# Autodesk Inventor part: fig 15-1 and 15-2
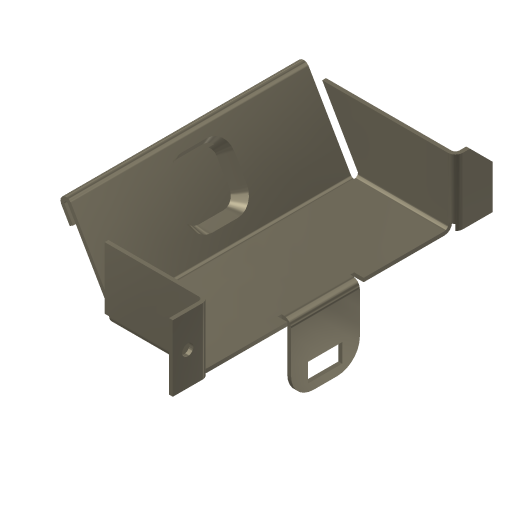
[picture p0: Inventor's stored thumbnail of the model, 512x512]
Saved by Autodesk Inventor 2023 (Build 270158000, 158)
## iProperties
Created: 2002-04
Part Number: fig 15-1 and 15-2
Material: Stainless Steel, 440C
Document SubType Name: Sheet Metal
Density: 1 g/cm^3
Sheet Metal Rule: Default
Appearance: Metal-Titanium (Polished)
Control State: 0
Master: False
Checked Out: False
Shininess: 65.0
Angle Display Precision: 2
Document Length Units: 11269
Document Angle Units: 11279
Document Time Units: 11290
Document Mass Units: 11283
Document Length Units Precision: 3
Document Angle Units Precision: 2
Compacted: False
Density: 0.0
Volumn: 0.0
Area: 0.0
PropertySet Name: Model Information
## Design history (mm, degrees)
node "Face1"
  sketch "Sketch1"
    geometry: L1 (-46.618, 22.343)-(-46.618, -12.657); L2 (-46.618, -12.657)-(53.382, -12.657); L3 (53.382, -12.657)-(53.382, 22.343); L4 (53.382, 22.343)-(35.882, 22.343); L5 (35.882, 22.343)-(35.882, 12.343); L6 (35.882, 12.343)-(-29.118, 12.343); L7 (-29.118, 12.343)-(-29.118, 22.343); L8 (-29.118, 22.343)-(-46.618, 22.343)
    constraints: 16 end point, 6 parallel, 2 equal length, 1 perpendicular, 1 vertical
    dimensions: "d0" = 100 distance of L1.end L2.end; "d1" = 35 distance of L1.start L1.end; "d2" = 65 distance of L5.end L6.end; "d3" = 10 distance of L6.end L7.end
sketch "Sketch2"
  geometry: L1 (100, 0)-(0, 0) reference; L2 (17.5, 35)-(17.5, 25) reference; L3 (17.5, 25)-(17.5, 0); L4 (82.5, 25)-(82.5, 0)
  constraints: 4 end point, 2 point on line, 1 collinear, 1 perpendicular
feature "Fold1" dims "d5" = 1 (= BendRadius), "d6" = 90 deg, "d7" = 1 (= BendRadius), "d52" = 1 (= BendReliefWidth), "d53" = 0.5 (= BendReliefDepth), "d54" = 2 (= MinimumRemnant), "d75" = 1 (= Thickness), "SeamGap" = 0.01
feature "Fold2" dims "d8" = 1 (= BendRadius), "d9" = 90 deg, "d10" = 1 (= BendRadius), "d55" = 1 (= BendReliefWidth), "d56" = 0.5 (= BendReliefDepth), "d57" = 2 (= MinimumRemnant), "d75" = 1 (= Thickness), "SeamGap" = 0.01
node "Flange1"
feature "Corner1" dims "d15" = 1 (= Thickness), "d16" = 0, "d73" = 4 (= CornerReliefSize), "d75" = 1 (= Thickness), "TransitionRadius" = 1 (= BendRadius)
sketch "Sketch4"
  geometry: L1 (0, 0)-(0, 35) reference; L2 (15.869, 25)-(15.869, 26) reference; L3 (17.5, 26)-(0, 26)
  constraints: 2 end point, 1 perpendicular, 1 point on line
feature "Fold3" sketch "Sketch4" dims "d17" = 1 (= BendRadius), "d18" = 90 deg, "d19" = 1 (= BendRadius), "d61" = 1 (= BendReliefWidth), "d62" = 0.5 (= BendReliefDepth), "d63" = 2 (= MinimumRemnant), "d75" = 1 (= Thickness), "SeamGap" = 0.01
sketch "Sketch5"
  geometry: L1 (-17.5, -34.296)-(-17.5, 9) reference; L2 (0, 0)-(-17.5, 0)
  constraints: 2 end point, 1 perpendicular, 1 point on line
feature "Fold4" sketch "Sketch5" dims "d20" = 1 (= BendRadius), "d21" = 90 deg, "d22" = 1 (= BendRadius), "d64" = 1 (= BendReliefWidth), "d65" = 0.5 (= BendReliefDepth), "d66" = 2 (= MinimumRemnant), "d75" = 1 (= Thickness), "SeamGap" = 0.01
sketch "Sketch6"
  geometry: 1 further point
feature "iFeature4:1" sketch "Sketch6"
feature "Hem2" dims "d32" = 1 (= BendRadius), "d33" = 6 (= 6 x Thickness), "d34" = 1 (= Thickness), "d35" = 0.5 (= 0.5 x d34), "d67" = 1 (= BendReliefWidth), "d68" = 0.5 (= BendReliefDepth), "d69" = 2 (= MinimumRemnant), "d75" = 1 (= Thickness), "SeamGap" = 0.01, "MinimumRemnant" = 2 (= 2 x Thickness), "BendReliefWidth" = 1 (= Thickness)
node "Face2"
  sketch "Sketch9"
    geometry: L1 (0, 0)-(62.738, 0) reference; L2 (40.511, 0)-(22.35, 0); L3 (22.35, 0)-(22.35, 18.987); L4 (22.35, 18.987)-(40.511, 18.987); L5 (40.511, 18.987)-(40.511, 0)
    constraints: 8 end point, 2 parallel, 1 horizontal, 1 perpendicular, 1 point on line
sketch "Sketch10"
  geometry: L1 (13.661, -2.202)-(4.661, -2.202); L2 (4.661, -2.202)-(4.661, -7.127); L3 (4.661, -7.127)-(13.661, -7.127); L4 (13.661, -7.127)-(13.661, -2.202); L5 (18.161, -16.987)-(18.161, 0) reference
  constraints: 8 end point, 2 parallel, 1 horizontal, 1 perpendicular
  dimensions: "d50" = 4.5 distance between parallel lines of L5 L4; "d51" = 9 distance of L1.start L1.end
cut "Cut1" sketch "Sketch10" dims "d38" = 1 (= Thickness), "d39" = 0
sketch "Sketch11"
  geometry: 1 further point
hole "Hole1" sketch "Sketch11" at (3.935, 8.75) diameter "d40" = 3; stored, may be unused: countersink angle "d44" = 82 deg, drill point angle "d46" = 118 deg; dims "d41" = 6, "d42" = 4, "d43" = 2, "d45" = 8
feature "Corner Chamfer1" dims "d47" = 6, "d48" = 6, angle "d74" = 45 deg
feature "Corner Round1" dims "d49" = 6
body "Solid1"
face "Plate1" dims "d75" = 1 (= Thickness)
sketch "Sketch3"
  geometry: L1 (-62.738, 0)-(-62.738, 25); L2 (-62.738, 25)-(0, 25); 1 other entity
  constraints: 4 end point, 4 other
face "Plate2" dims "d12" = 25, "d13" = 120 deg, "d14" = 1 (= BendRadius), "d75" = 1 (= Thickness), "MinimumRemnant" = 2 (= 2 x Thickness), "BendReliefWidth" = 1 (= Thickness)
bend "Bend1" dims "d11" = 1 (= BendRadius), "d12" = 25, "d13" = 120 deg, "d14" = 1 (= BendRadius), "d58" = 1 (= BendReliefWidth), "d59" = 0.5 (= BendReliefDepth), "d60" = 2 (= MinimumRemnant), "d75" = 1 (= Thickness), "SeamGap" = 0.01, "MinimumRemnant" = 2 (= 2 x Thickness), "BendReliefWidth" = 1 (= Thickness)
sketch "Sketch8"
  geometry: L1 (0.866, 0.5)-(0, 0); L2 (-0.866, -0.5)-(1.384, -4.397); L3 (1.384, -4.397)-(0.518, -4.897); L4 (0.518, -4.897)-(-1.732, -1); A1 r 0.5 centre (-0.433, -0.25) between (0, 0) and (-0.866, -0.5); A2 r 1.5 centre (-0.433, -0.25) between (0.866, 0.5) and (-1.732, -1)
  constraints: 8 end point, 4 point on circle
face "Plate3" dims "d36" = 1 (= BendRadius), "d75" = 1 (= Thickness), "MinimumRemnant" = 2 (= 2 x Thickness), "BendReliefWidth" = 1 (= Thickness)
bend "Bend2" dims "d36" = 1 (= BendRadius), "d37" = 1 (= BendRadius), "d70" = 1 (= BendReliefWidth), "d71" = 0.5 (= BendReliefDepth), "d72" = 2 (= MinimumRemnant), "d75" = 1 (= Thickness), "SeamGap" = 0.01, "MinimumRemnant" = 2 (= 2 x Thickness), "BendReliefWidth" = 1 (= Thickness)
other parameters: "Thickness" = 1, "BendRadius" = 1 (= Thickness), "BendReliefDepth" = 0.5 (= 0.5 x Thickness), "CornerReliefSize" = 4 (= 4 x Thickness), "d4" = 1 (= BendRadius), "d27" = 0, "JacobiRadiusSize" = 1 (= Thickness), "GapSize" = 1 (= Thickness)
